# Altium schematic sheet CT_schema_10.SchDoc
size 274 x 160 mm
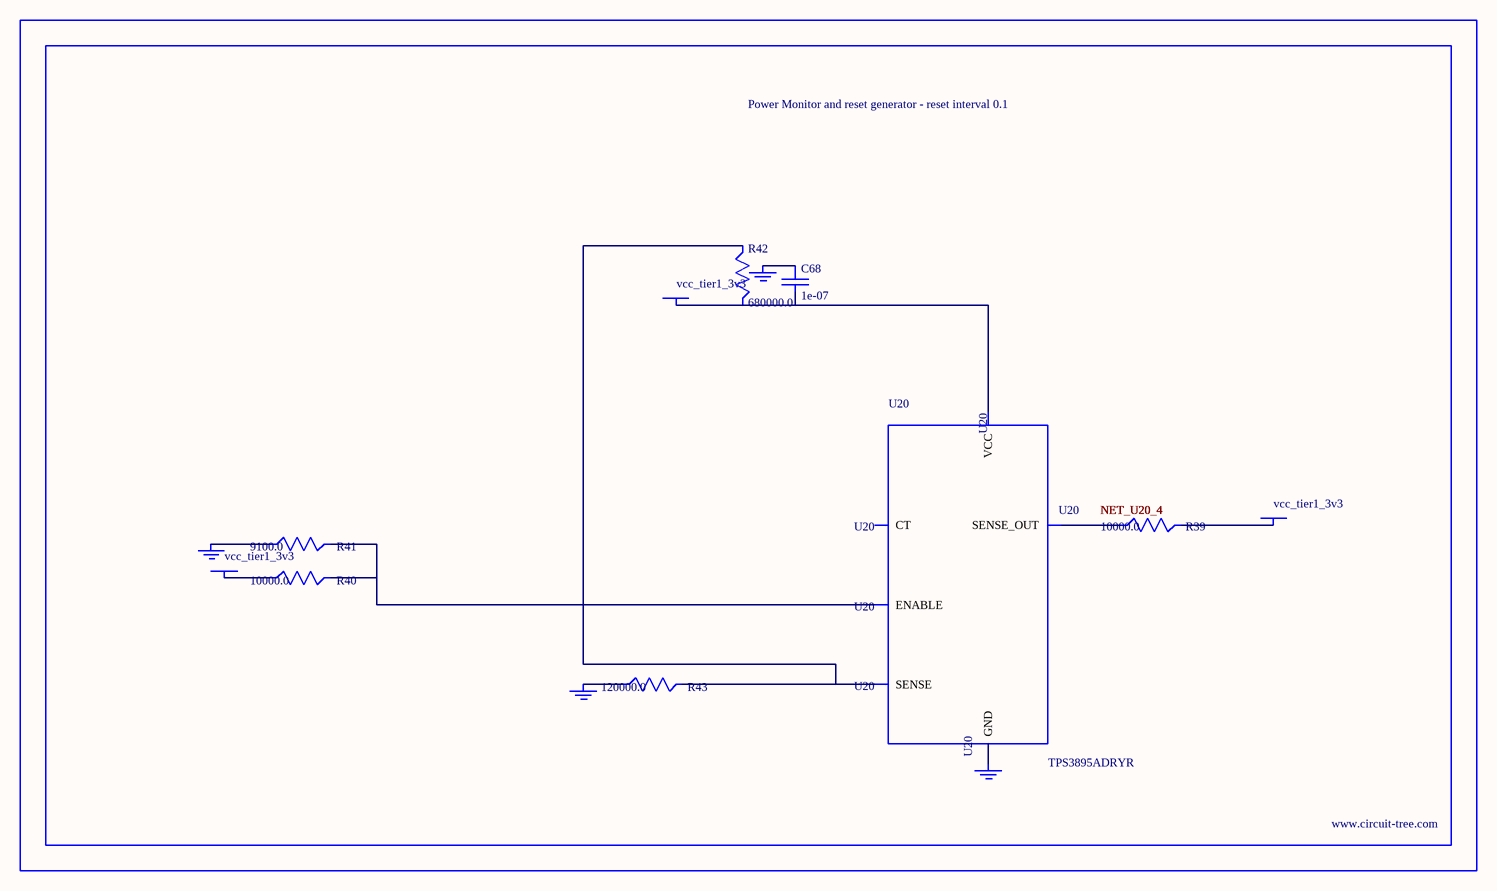
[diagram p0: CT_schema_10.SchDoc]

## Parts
BORDER9  (no value)
C68  1e-07  [C0402]
GND_INSTANCE_9_0  (no value)
GND_INSTANCE_9_1  (no value)
GND_INSTANCE_9_2  (no value)
GND_INSTANCE_9_3  (no value)
POWER_INSTANCE_9_0  vcc_tier1_3v3
POWER_INSTANCE_9_1  vcc_tier1_3v3
POWER_INSTANCE_9_2  vcc_tier1_3v3
R39  10000.0  [R0603]
R40  10000.0  [R0603]
R41  9100.0  [R0603]
R42  680000.0  [R0603]
R43  120000.0  [R0603]
U20  TPS3895ADRYR  [SON-6]

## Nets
NetC68_1: C68.1 GND_INSTANCE_9_2.0(GND)
NetC68_2: C68.2 POWER_INSTANCE_9_2.0(PWR) R42.2 U20.6(VCC)
NetGND_INSTANCE_9_0_0: GND_INSTANCE_9_0.0(GND) R41.1
NetGND_INSTANCE_9_1_0: GND_INSTANCE_9_1.0(GND) R43.1
NetGND_INSTANCE_9_3_0: GND_INSTANCE_9_3.0(GND) U20.2(GND)
NetPOWER_INSTANCE_9_0_0: POWER_INSTANCE_9_0.0(PWR) R40.1
NetPOWER_INSTANCE_9_1_0: POWER_INSTANCE_9_1.0(PWR) R39.2
NetR39_1: R39.1 U20.4(SENSE_OUT)
NetR40_2: R40.2 R41.2 U20.1(ENABLE)
NetR42_1: R42.1 R43.2 U20.3(SENSE)

Not connected (* = marked no-connect by the designer): U20 5(CT)

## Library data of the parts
BORDER9 = BORDER_PAGE9
C68 = C0402C104K3RACTU
GND_INSTANCE_9_0-GND_INSTANCE_9_3 = GND
POWER_INSTANCE_9_0-POWER_INSTANCE_9_2 = PWR
R39 R40 = RC0603JR-0710KL
R41 = RC0603JR-079K1L
R42 = RC0603JR-07680KL
R43 = RC0603JR-07120KL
